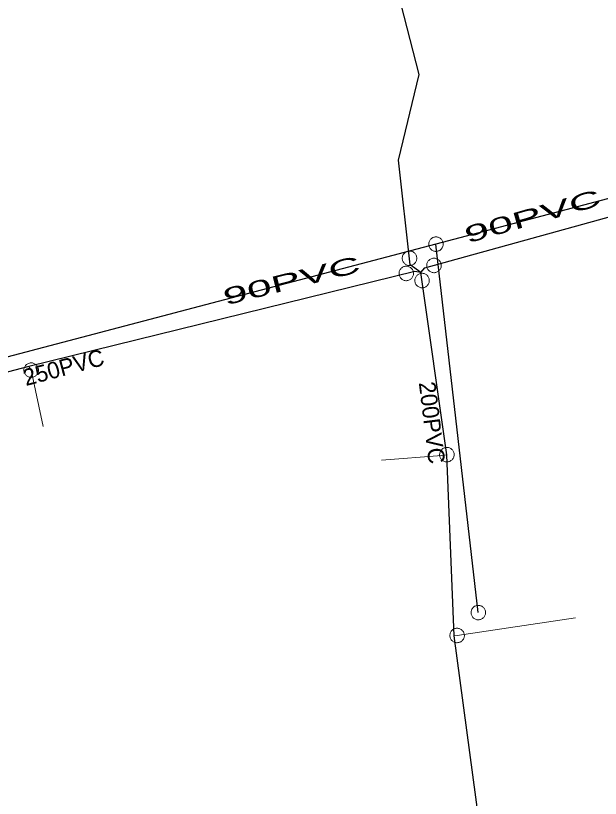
# Model space of a CAD drawing. Extents: x -741806 to -738704, y -1059275 to -1055387.
# Drawn here: x -740624.24 to -740588.96, y -1057303.2 to -1057256 of the extents above; entities that cross this region are included whole.
import ezdxf

# ---------------------------------------------------------------- set-up
doc = ezdxf.new("R2010")
doc.units = 0
doc.header["$LTSCALE"] = 0.4
for name, color, linetype, lineweight in [('2', 7, 'Continuous', 25), ('21', 7, 'Continuous', 13), ('3', 7, 'Continuous', 13), ('51', 7, 'Continuous', 13), ('52', 7, 'Continuous', 25)]:
    doc.layers.add(name, color=color, linetype=linetype, lineweight=lineweight)
doc.layers.add('5', color=7, linetype='Continuous')
doc.layers.add('53', color=7, linetype='Continuous')

msp = doc.modelspace()

# ---------------------------------------------------------------- linework, layer by layer
at = {"layer": '2'}
for p in [(-740573.78, -1057263.169), (-740596.329, -1057292)]:
    msp.add_line(p, (-740598.879, -1057269.78), dxfattribs=at)
msp.add_lwpolyline([(-740598.879, -1057269.78), (-740643.57, -1057281.54), (-740672.23, -1057290.27), (-740701.8, -1057300.899)], dxfattribs=at)
at = {"layer": '21'}
for points in [[(-740623.436, -1057277.166), (-740623.3, -1057277.379), (-740622.572, -1057280.771)], [(-740598.223, -1057282.477), (-740598.526, -1057282.531), (-740602.17, -1057282.806)], [(-740597.782, -1057293.399), (-740597.605, -1057293.378), (-740590.458, -1057292.324)]]:
    msp.add_lwpolyline(points, dxfattribs=at)
at = {"layer": '3'}
for points in [[(-740598.928, -1057269.344), (-740598.972, -1057269.352), (-740599.016, -1057269.364), (-740599.06, -1057269.382), (-740599.099, -1057269.402), (-740599.138, -1057269.428), (-740599.174, -1057269.457), (-740599.205, -1057269.49), (-740599.234, -1057269.525), (-740599.258, -1057269.564), (-740599.279, -1057269.605), (-740599.295, -1057269.648), (-740599.307, -1057269.693), (-740599.313, -1057269.738), (-740599.315, -1057269.783), (-740599.312, -1057269.829), (-740599.305, -1057269.875), (-740599.292, -1057269.919), (-740599.276, -1057269.961), (-740599.254, -1057270.002), (-740599.229, -1057270.04), (-740599.199, -1057270.075), (-740599.168, -1057270.107), (-740599.131, -1057270.136), (-740599.093, -1057270.16), (-740599.051, -1057270.181), (-740599.008, -1057270.196), (-740598.965, -1057270.208), (-740598.919, -1057270.215), (-740598.873, -1057270.217), (-740598.827, -1057270.213), (-740598.783, -1057270.206), (-740598.739, -1057270.194), (-740598.695, -1057270.177), (-740598.655, -1057270.155), (-740598.617, -1057270.131), (-740598.581, -1057270.102), (-740598.55, -1057270.069), (-740598.521, -1057270.032), (-740598.497, -1057269.994), (-740598.477, -1057269.954), (-740598.46, -1057269.911), (-740598.448, -1057269.866), (-740598.441, -1057269.821), (-740598.44, -1057269.775), (-740598.443, -1057269.73), (-740598.45, -1057269.684), (-740598.462, -1057269.64), (-740598.479, -1057269.598), (-740598.501, -1057269.557), (-740598.526, -1057269.519), (-740598.556, -1057269.484), (-740598.588, -1057269.451), (-740598.624, -1057269.423), (-740598.662, -1057269.398), (-740598.704, -1057269.378), (-740598.747, -1057269.362), (-740598.79, -1057269.351), (-740598.836, -1057269.344), (-740598.882, -1057269.342), (-740598.927, -1057269.344)], [(-740596.378, -1057291.564), (-740596.422, -1057291.572), (-740596.466, -1057291.584), (-740596.51, -1057291.602), (-740596.549, -1057291.622), (-740596.588, -1057291.648), (-740596.624, -1057291.677), (-740596.655, -1057291.71), (-740596.684, -1057291.745), (-740596.708, -1057291.784), (-740596.729, -1057291.825), (-740596.745, -1057291.868), (-740596.757, -1057291.913), (-740596.763, -1057291.958), (-740596.765, -1057292.003), (-740596.762, -1057292.049), (-740596.755, -1057292.095), (-740596.742, -1057292.139), (-740596.726, -1057292.181), (-740596.704, -1057292.222), (-740596.679, -1057292.26), (-740596.649, -1057292.295), (-740596.618, -1057292.327), (-740596.581, -1057292.356), (-740596.543, -1057292.38), (-740596.501, -1057292.401), (-740596.458, -1057292.416), (-740596.415, -1057292.428), (-740596.369, -1057292.435), (-740596.323, -1057292.437), (-740596.277, -1057292.433), (-740596.233, -1057292.426), (-740596.189, -1057292.414), (-740596.145, -1057292.397), (-740596.105, -1057292.375), (-740596.067, -1057292.351), (-740596.031, -1057292.322), (-740596, -1057292.289), (-740595.971, -1057292.252), (-740595.947, -1057292.214), (-740595.927, -1057292.174), (-740595.91, -1057292.131), (-740595.898, -1057292.086), (-740595.891, -1057292.041), (-740595.89, -1057291.995), (-740595.893, -1057291.95), (-740595.9, -1057291.904), (-740595.912, -1057291.86), (-740595.929, -1057291.818), (-740595.951, -1057291.777), (-740595.976, -1057291.739), (-740596.006, -1057291.704), (-740596.038, -1057291.671), (-740596.074, -1057291.643), (-740596.112, -1057291.618), (-740596.154, -1057291.598), (-740596.197, -1057291.582), (-740596.24, -1057291.571), (-740596.286, -1057291.564), (-740596.332, -1057291.562), (-740596.377, -1057291.564)]]:
    msp.add_lwpolyline(points, dxfattribs=at)
at = {"layer": '51'}
for points in [[(-740600.038, -1057270.632), (-740600.039, -1057270.587), (-740600.047, -1057270.542), (-740600.059, -1057270.497), (-740600.075, -1057270.455), (-740600.096, -1057270.414), (-740600.12, -1057270.375), (-740600.15, -1057270.34), (-740600.182, -1057270.307), (-740600.218, -1057270.279), (-740600.255, -1057270.254), (-740600.297, -1057270.233), (-740600.34, -1057270.216), (-740600.384, -1057270.204), (-740600.429, -1057270.197), (-740600.475, -1057270.195), (-740600.521, -1057270.197), (-740600.566, -1057270.204), (-740600.61, -1057270.216), (-740600.652, -1057270.233), (-740600.694, -1057270.254), (-740600.732, -1057270.279), (-740600.767, -1057270.307), (-740600.799, -1057270.34), (-740600.829, -1057270.375), (-740600.853, -1057270.414), (-740600.875, -1057270.455), (-740600.891, -1057270.497), (-740600.902, -1057270.542), (-740600.91, -1057270.587), (-740600.913, -1057270.633), (-740600.91, -1057270.678), (-740600.902, -1057270.723), (-740600.891, -1057270.768), (-740600.875, -1057270.81), (-740600.853, -1057270.851), (-740600.829, -1057270.89), (-740600.799, -1057270.925), (-740600.767, -1057270.958), (-740600.732, -1057270.986), (-740600.694, -1057271.011), (-740600.652, -1057271.032), (-740600.61, -1057271.049), (-740600.566, -1057271.06), (-740600.521, -1057271.068), (-740600.475, -1057271.07), (-740600.429, -1057271.068), (-740600.384, -1057271.06), (-740600.34, -1057271.049), (-740600.297, -1057271.032), (-740600.255, -1057271.011), (-740600.218, -1057270.986), (-740600.182, -1057270.958), (-740600.15, -1057270.925), (-740600.12, -1057270.89), (-740600.096, -1057270.851), (-740600.075, -1057270.81), (-740600.059, -1057270.768), (-740600.047, -1057270.723), (-740600.039, -1057270.678), (-740600.038, -1057270.633)], [(-740598.579, -1057270.951), (-740598.593, -1057270.908), (-740598.612, -1057270.866), (-740598.635, -1057270.826), (-740598.662, -1057270.79), (-740598.693, -1057270.756), (-740598.728, -1057270.725), (-740598.765, -1057270.699), (-740598.805, -1057270.676), (-740598.847, -1057270.658), (-740598.89, -1057270.644), (-740598.935, -1057270.635), (-740598.981, -1057270.63), (-740599.027, -1057270.63), (-740599.072, -1057270.635), (-740599.117, -1057270.646), (-740599.161, -1057270.66), (-740599.202, -1057270.679), (-740599.241, -1057270.702), (-740599.278, -1057270.73), (-740599.312, -1057270.761), (-740599.342, -1057270.795), (-740599.369, -1057270.832), (-740599.391, -1057270.872), (-740599.41, -1057270.914), (-740599.424, -1057270.958), (-740599.433, -1057271.003), (-740599.437, -1057271.048), (-740599.437, -1057271.094), (-740599.432, -1057271.14), (-740599.422, -1057271.185), (-740599.407, -1057271.227), (-740599.389, -1057271.269), (-740599.365, -1057271.309), (-740599.338, -1057271.345), (-740599.307, -1057271.379), (-740599.273, -1057271.41), (-740599.236, -1057271.436), (-740599.196, -1057271.459), (-740599.154, -1057271.477), (-740599.11, -1057271.491), (-740599.065, -1057271.5), (-740599.019, -1057271.505), (-740598.974, -1057271.504), (-740598.929, -1057271.499), (-740598.884, -1057271.489), (-740598.84, -1057271.475), (-740598.799, -1057271.455), (-740598.759, -1057271.433), (-740598.722, -1057271.405), (-740598.688, -1057271.374), (-740598.658, -1057271.34), (-740598.631, -1057271.303), (-740598.609, -1057271.263), (-740598.59, -1057271.221), (-740598.577, -1057271.177), (-740598.567, -1057271.132), (-740598.563, -1057271.087), (-740598.564, -1057271.041), (-740598.569, -1057270.995), (-740598.579, -1057270.952)], [(-740601.097, -1057271.653), (-740601.084, -1057271.696), (-740601.067, -1057271.738), (-740601.044, -1057271.779), (-740601.019, -1057271.816), (-740600.988, -1057271.85), (-740600.955, -1057271.882), (-740600.918, -1057271.909), (-740600.879, -1057271.934), (-740600.838, -1057271.952), (-740600.795, -1057271.967), (-740600.75, -1057271.978), (-740600.704, -1057271.984), (-740600.658, -1057271.985), (-740600.613, -1057271.981), (-740600.568, -1057271.972), (-740600.524, -1057271.959), (-740600.482, -1057271.942), (-740600.442, -1057271.92), (-740600.404, -1057271.893), (-740600.369, -1057271.863), (-740600.339, -1057271.829), (-740600.31, -1057271.793), (-740600.287, -1057271.754), (-740600.267, -1057271.713), (-740600.252, -1057271.669), (-740600.242, -1057271.624), (-740600.236, -1057271.579), (-740600.236, -1057271.533), (-740600.24, -1057271.487), (-740600.248, -1057271.442), (-740600.261, -1057271.399), (-740600.279, -1057271.357), (-740600.301, -1057271.316), (-740600.327, -1057271.279), (-740600.357, -1057271.245), (-740600.391, -1057271.213), (-740600.427, -1057271.186), (-740600.466, -1057271.161), (-740600.508, -1057271.143), (-740600.551, -1057271.128), (-740600.596, -1057271.117), (-740600.641, -1057271.111), (-740600.687, -1057271.111), (-740600.732, -1057271.114), (-740600.778, -1057271.123), (-740600.822, -1057271.136), (-740600.864, -1057271.154), (-740600.904, -1057271.176), (-740600.941, -1057271.202), (-740600.976, -1057271.233), (-740601.007, -1057271.266), (-740601.035, -1057271.302), (-740601.058, -1057271.341), (-740601.078, -1057271.382), (-740601.093, -1057271.426), (-740601.104, -1057271.471), (-740601.109, -1057271.516), (-740601.11, -1057271.562), (-740601.106, -1057271.608), (-740601.097, -1057271.652)], [(-740599.781, -1057271.545), (-740599.825, -1057271.553), (-740599.868, -1057271.566), (-740599.911, -1057271.585), (-740599.951, -1057271.606), (-740599.988, -1057271.633), (-740600.023, -1057271.663), (-740600.054, -1057271.697), (-740600.082, -1057271.733), (-740600.105, -1057271.773), (-740600.124, -1057271.814), (-740600.139, -1057271.858), (-740600.15, -1057271.902), (-740600.156, -1057271.948), (-740600.156, -1057271.993), (-740600.152, -1057272.039), (-740600.143, -1057272.084), (-740600.13, -1057272.128), (-740600.112, -1057272.17), (-740600.089, -1057272.21), (-740600.062, -1057272.248), (-740600.032, -1057272.282), (-740599.999, -1057272.313), (-740599.962, -1057272.34), (-740599.923, -1057272.364), (-740599.881, -1057272.383), (-740599.838, -1057272.398), (-740599.794, -1057272.408), (-740599.748, -1057272.414), (-740599.702, -1057272.414), (-740599.656, -1057272.411), (-740599.612, -1057272.402), (-740599.569, -1057272.388), (-740599.526, -1057272.37), (-740599.486, -1057272.348), (-740599.449, -1057272.322), (-740599.414, -1057272.291), (-740599.383, -1057272.258), (-740599.355, -1057272.222), (-740599.332, -1057272.182), (-740599.313, -1057272.141), (-740599.298, -1057272.097), (-740599.287, -1057272.052), (-740599.282, -1057272.007), (-740599.281, -1057271.961), (-740599.285, -1057271.916), (-740599.294, -1057271.87), (-740599.308, -1057271.827), (-740599.325, -1057271.785), (-740599.348, -1057271.745), (-740599.375, -1057271.707), (-740599.405, -1057271.673), (-740599.438, -1057271.641), (-740599.475, -1057271.614), (-740599.514, -1057271.591), (-740599.556, -1057271.571), (-740599.599, -1057271.556), (-740599.643, -1057271.546), (-740599.689, -1057271.541), (-740599.735, -1057271.54), (-740599.78, -1057271.545)], [(-740623.064, -1057277.746), (-740623.027, -1057277.72), (-740622.993, -1057277.69), (-740622.961, -1057277.656), (-740622.935, -1057277.619), (-740622.912, -1057277.58), (-740622.892, -1057277.537), (-740622.879, -1057277.494), (-740622.868, -1057277.449), (-740622.864, -1057277.404), (-740622.864, -1057277.358), (-740622.868, -1057277.313), (-740622.877, -1057277.267), (-740622.891, -1057277.224), (-740622.909, -1057277.182), (-740622.932, -1057277.142), (-740622.959, -1057277.105), (-740622.989, -1057277.071), (-740623.023, -1057277.04), (-740623.061, -1057277.013), (-740623.1, -1057276.99), (-740623.142, -1057276.972), (-740623.185, -1057276.957), (-740623.23, -1057276.947), (-740623.275, -1057276.942), (-740623.322, -1057276.942), (-740623.367, -1057276.947), (-740623.411, -1057276.956), (-740623.456, -1057276.97), (-740623.497, -1057276.989), (-740623.538, -1057277.011), (-740623.574, -1057277.038), (-740623.608, -1057277.068), (-740623.639, -1057277.102), (-740623.666, -1057277.139), (-740623.689, -1057277.178), (-740623.708, -1057277.221), (-740623.722, -1057277.264), (-740623.733, -1057277.309), (-740623.737, -1057277.354), (-740623.737, -1057277.4), (-740623.733, -1057277.445), (-740623.724, -1057277.491), (-740623.709, -1057277.534), (-740623.692, -1057277.576), (-740623.668, -1057277.616), (-740623.642, -1057277.653), (-740623.611, -1057277.687), (-740623.578, -1057277.718), (-740623.54, -1057277.745), (-740623.5, -1057277.768), (-740623.459, -1057277.786), (-740623.416, -1057277.802), (-740623.371, -1057277.811), (-740623.325, -1057277.816), (-740623.279, -1057277.816), (-740623.233, -1057277.811), (-740623.189, -1057277.802), (-740623.145, -1057277.788), (-740623.103, -1057277.77), (-740623.064, -1057277.747)], [(-740598.653, -1057282.553), (-740598.643, -1057282.597), (-740598.628, -1057282.64), (-740598.608, -1057282.682), (-740598.585, -1057282.72), (-740598.557, -1057282.757), (-740598.526, -1057282.791), (-740598.491, -1057282.821), (-740598.454, -1057282.847), (-740598.414, -1057282.869), (-740598.372, -1057282.887), (-740598.328, -1057282.9), (-740598.283, -1057282.909), (-740598.237, -1057282.913), (-740598.192, -1057282.912), (-740598.146, -1057282.906), (-740598.101, -1057282.896), (-740598.058, -1057282.881), (-740598.017, -1057282.862), (-740597.977, -1057282.838), (-740597.941, -1057282.81), (-740597.908, -1057282.778), (-740597.877, -1057282.745), (-740597.851, -1057282.706), (-740597.829, -1057282.667), (-740597.811, -1057282.624), (-740597.798, -1057282.58), (-740597.789, -1057282.536), (-740597.785, -1057282.49), (-740597.786, -1057282.444), (-740597.792, -1057282.398), (-740597.802, -1057282.354), (-740597.817, -1057282.311), (-740597.837, -1057282.269), (-740597.86, -1057282.231), (-740597.888, -1057282.194), (-740597.919, -1057282.16), (-740597.954, -1057282.131), (-740597.991, -1057282.104), (-740598.032, -1057282.082), (-740598.073, -1057282.064), (-740598.118, -1057282.051), (-740598.163, -1057282.042), (-740598.208, -1057282.039), (-740598.254, -1057282.039), (-740598.299, -1057282.045), (-740598.344, -1057282.055), (-740598.387, -1057282.071), (-740598.429, -1057282.089), (-740598.468, -1057282.113), (-740598.505, -1057282.141), (-740598.538, -1057282.173), (-740598.568, -1057282.206), (-740598.594, -1057282.245), (-740598.616, -1057282.284), (-740598.634, -1057282.327), (-740598.648, -1057282.371), (-740598.656, -1057282.415), (-740598.66, -1057282.462), (-740598.659, -1057282.507), (-740598.653, -1057282.552)], [(-740597.171, -1057293.326), (-740597.178, -1057293.282), (-740597.19, -1057293.238), (-740597.207, -1057293.195), (-740597.228, -1057293.155), (-740597.254, -1057293.117), (-740597.283, -1057293.081), (-740597.316, -1057293.05), (-740597.352, -1057293.021), (-740597.391, -1057292.997), (-740597.432, -1057292.977), (-740597.475, -1057292.961), (-740597.52, -1057292.949), (-740597.565, -1057292.942), (-740597.61, -1057292.941), (-740597.656, -1057292.944), (-740597.702, -1057292.952), (-740597.746, -1057292.964), (-740597.788, -1057292.981), (-740597.828, -1057293.003), (-740597.867, -1057293.029), (-740597.901, -1057293.058), (-740597.934, -1057293.09), (-740597.962, -1057293.127), (-740597.986, -1057293.165), (-740598.007, -1057293.206), (-740598.023, -1057293.25), (-740598.034, -1057293.293), (-740598.04, -1057293.339), (-740598.042, -1057293.385), (-740598.039, -1057293.431), (-740598.031, -1057293.475), (-740598.019, -1057293.519), (-740598.001, -1057293.562), (-740597.981, -1057293.602), (-740597.955, -1057293.64), (-740597.925, -1057293.676), (-740597.892, -1057293.707), (-740597.857, -1057293.736), (-740597.818, -1057293.76), (-740597.777, -1057293.78), (-740597.734, -1057293.796), (-740597.689, -1057293.808), (-740597.644, -1057293.814), (-740597.598, -1057293.816), (-740597.553, -1057293.813), (-740597.507, -1057293.805), (-740597.463, -1057293.792), (-740597.421, -1057293.776), (-740597.38, -1057293.754), (-740597.342, -1057293.728), (-740597.307, -1057293.699), (-740597.275, -1057293.667), (-740597.247, -1057293.63), (-740597.222, -1057293.592), (-740597.202, -1057293.551), (-740597.186, -1057293.507), (-740597.175, -1057293.464), (-740597.169, -1057293.418), (-740597.167, -1057293.372), (-740597.17, -1057293.327)]]:
    msp.add_lwpolyline(points, dxfattribs=at)
at = {"layer": '52'}
for points in [[(-740599.789, -1057271.49), (-740600.43, -1057271.03), (-740601.149, -1057264.71), (-740599.89, -1057259.55), (-740605.469, -1057237.879), (-740606.21, -1057235.75), (-740610.079, -1057216.44), (-740610.699, -1057213.46), (-740613.21, -1057198.96), (-740635.57, -1057204.919), (-740654.67, -1057209.71), (-740658.96, -1057210.78), (-740671.342, -1057213.918), (-740678.14, -1057215.639), (-740680.199, -1057216.11)], [(-740599.789, -1057271.49), (-740599.544, -1057271.217), (-740577.079, -1057265.007), (-740575.563, -1057264.566), (-740574.636, -1057264.455), (-740573.886, -1057264.318), (-740573.23, -1057264.149)], [(-740599.789, -1057271.49), (-740600.159, -1057271.422), (-740623.436, -1057277.166), (-740641.474, -1057281.881), (-740643.675, -1057282.756), (-740644.41, -1057282.96)], [(-740592.169, -1057336.51), (-740592.884, -1057329.919), (-740597.782, -1057293.399), (-740598.223, -1057282.477), (-740599.789, -1057271.49)]]:
    msp.add_lwpolyline(points, dxfattribs=at)

# ---------------------------------------------------------------- texts
at = {"layer": '5'}
for s, rotation, p in [('250PVC', 15, (-740623.62, -1057278.342)), ('200PVC', 277, (-740599.918, -1057278.135))]:
    msp.add_text(s, height=1, rotation=rotation, dxfattribs=at).set_placement(p)
at = {"layer": '53', "width": 2}
for rotation, p in [(16, (-740596.991, -1057269.745)), (14, (-740611.583, -1057273.483))]:
    msp.add_text('90PVC ', height=1, rotation=rotation, dxfattribs=at).set_placement(p)

doc.saveas('drawing.dxf')
